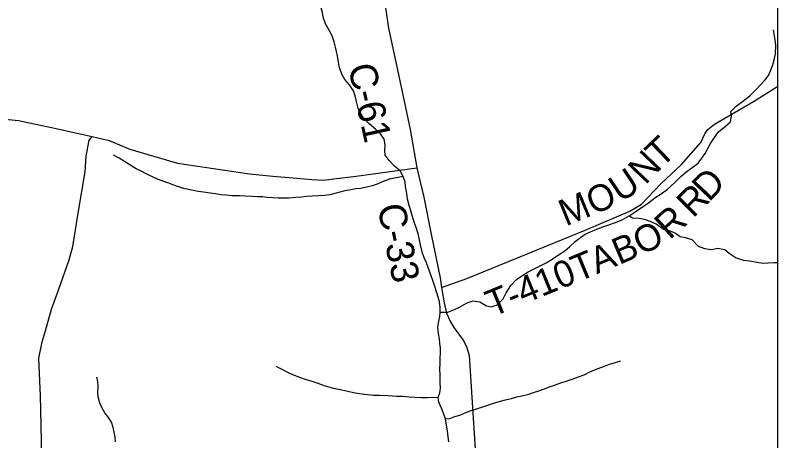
# Model space of a CAD drawing. Extents: x -139 to 835, y 0 to 440.
# Drawn here: x 242.7 to 295.5, y 288.9 to 318.3 of the extents above; entities that cross this region are included whole.
import ezdxf

# ---------------------------------------------------------------- set-up
doc = ezdxf.new("R2010")
doc.units = 0
for name, color, linetype in [('GM_X_County_Road', 7, 'Continuous'), ('GM_X_County_Road_Text', 7, 'Continuous'), ('GM_X_County_Text', 7, 'Continuous'), ('GM_X_Minor_River', 7, 'Continuous'), ('GM_X_Township_Road', 7, 'Continuous'), ('GM_X_Township_Road_Text', 7, 'Continuous'), ('SH_Cut_Line', 7, 'Continuous')]:
    doc.layers.add(name, color=color, linetype=linetype)

msp = doc.modelspace()

# ---------------------------------------------------------------- linework, layer by layer
at = {"layer": 'GM_X_County_Road'}
for points in [[(267.916, 321.522), (268.508, 317.419), (269.147, 314.522), (270.024, 310.408), (270.486, 307.753)], [(241.269, 311.192), (242.908, 311.03), (245.196, 310.545), (247.995, 309.929), (249.19, 309.638), (250.624, 309.055), (253.902, 308.084), (258.899, 307.34), (260.514, 307.178), (261.925, 307.054), (263.209, 306.953), (263.997, 306.903), (264.722, 306.997), (266.287, 307.174), (270.486, 307.753)], [(270.486, 307.753), (270.962, 305.725), (271.487, 303.058), (272.101, 300.138), (272.175, 299.474), (272.375, 298.412), (272.538, 297.712), (272.816, 297.096), (273.043, 296.71), (273.676, 295.827), (273.917, 295.405), (274.092, 294.765), (274.624, 286.489)]]:
    msp.add_lwpolyline(points, dxfattribs=at)
at = {"layer": 'GM_X_County_Text'}
msp.add_lwpolyline([(138.399, 185.387), (295.458, 185.387), (295.458, 319.381), (267.909, 321.538), (228.151, 324.569)], dxfattribs=at)
at = {"layer": 'GM_X_Minor_River'}
for points in [[(264.747, 316.458), (264.616, 316.879), (264.422, 317.227), (264.15, 317.707), (263.993, 318.176), (263.939, 318.489), (263.86, 318.826), (263.818, 319.188), (263.789, 319.585), (263.543, 320.017), (263.057, 320.29), (262.637, 320.299), (262.192, 320.294), (261.848, 320.328), (261.4, 320.553), (261.053, 320.947), (260.795, 321.367), (260.335, 322.107)], [(272.098, 297.781), (272.632, 297.774), (273.089, 297.947), (273.431, 298.119), (273.912, 298.389), (274.356, 298.562), (274.827, 298.482), (275.301, 298.221), (275.62, 298.139), (276.038, 298.276), (276.442, 298.702), (276.667, 299.102), (276.98, 299.623), (277.384, 300.037), (277.75, 300.294), (278.181, 300.563), (278.916, 300.92), (279.422, 301.19), (279.84, 301.435), (280.282, 301.74), (280.712, 302.022), (281.041, 302.29), (281.445, 302.668), (281.799, 302.936), (282.127, 303.168), (282.495, 303.329), (282.926, 303.514), (283.357, 303.674), (283.763, 303.823), (284.169, 303.947), (284.689, 304.157), (285.17, 304.439), (285.663, 304.757), (286.169, 305.111), (286.523, 305.344), (286.94, 305.673), (287.383, 305.967), (287.826, 306.284), (288.343, 306.748), (288.759, 307.149), (289.189, 307.515), (289.517, 307.76), (289.947, 308.089), (290.211, 308.429), (290.437, 308.757), (290.813, 309.436), (291.126, 309.933), (291.365, 310.237), (291.833, 310.627), (292.199, 310.944), (292.246, 311.331), (292.205, 311.656), (292.571, 312.009), (293.026, 312.339), (293.518, 312.73), (293.922, 313.131), (294.288, 313.521), (294.59, 313.837), (294.829, 314.141), (294.966, 314.456), (295.128, 314.867), (295.238, 315.315), (295.299, 315.653), (295.319, 316.172), (295.291, 316.473), (295.224, 316.894), (295.169, 317.304)], [(272.689, 288.8), (272.648, 289.149), (272.593, 289.571), (272.539, 289.968), (272.458, 290.39), (272.302, 290.823), (272.184, 291.135), (272.002, 291.556), (271.961, 291.869), (272.06, 292.196), (272.108, 292.522), (272.092, 292.92), (272.087, 293.426), (272.07, 293.848), (272.092, 294.211), (272.101, 294.609), (272.111, 294.947), (272.108, 295.308), (272.079, 295.61), (272.038, 295.935), (271.984, 296.296), (271.942, 296.73), (271.989, 297.153), (272.062, 297.479), (272.098, 297.781), (272.095, 298.095), (272.04, 298.492), (271.948, 298.805), (271.738, 299.479), (271.607, 299.888), (271.437, 300.357), (271.255, 300.862), (271.137, 301.174), (271.007, 301.487), (270.864, 301.859), (270.731, 302.425), (270.651, 302.786), (270.559, 303.183), (270.427, 303.628), (270.297, 303.989), (270.166, 304.398), (270.06, 304.771), (269.942, 305.156), (269.836, 305.589), (269.782, 305.987), (269.701, 306.456), (269.66, 306.757), (269.542, 307.154), (269.322, 307.551), (268.925, 307.873), (268.552, 308.255), (268.294, 308.639), (268.265, 308.964), (268.287, 309.338), (268.207, 309.736), (267.962, 310.095), (267.616, 310.418), (267.167, 310.787), (266.781, 311.194), (266.549, 311.578), (266.406, 311.89), (266.3, 312.336), (266.207, 312.733), (266.102, 313.082), (265.818, 313.489), (265.496, 313.872), (265.303, 314.196), (265.12, 314.665), (264.985, 315.484), (264.919, 315.797), (264.852, 316.097), (264.747, 316.458)], [(269.542, 307.154), (268.92, 307.04), (268.589, 306.977), (268.158, 306.804), (267.74, 306.631), (267.397, 306.508), (267.004, 306.408), (266.584, 306.331), (266.254, 306.304), (265.911, 306.241), (265.504, 306.153), (265.149, 306.065), (264.463, 305.89), (264.056, 305.838), (263.637, 305.81), (263.242, 305.794), (262.861, 305.767), (262.467, 305.727), (262.098, 305.699), (261.614, 305.659), (261.258, 305.656), (260.889, 305.664), (260.482, 305.672), (260.125, 305.705), (259.794, 305.739), (259.425, 305.759), (259.094, 305.78), (258.584, 305.788), (258.202, 305.809), (257.68, 305.828), (257.26, 305.86), (256.916, 305.893), (256.534, 305.95), (256.164, 305.995), (255.706, 306.063), (255.336, 306.12), (254.89, 306.2), (254.316, 306.328), (253.984, 306.445), (253.665, 306.563), (253.307, 306.693), (252.963, 306.81), (252.643, 306.928), (252.311, 307.07), (251.8, 307.318), (251.391, 307.532), (251.045, 307.697), (250.687, 307.911), (250.316, 308.137), (249.881, 308.422), (249.484, 308.636)], [(285.17, 304.439), (285.413, 304.308), (285.859, 304.276), (286.203, 304.195), (286.663, 304.054), (287.11, 303.829), (287.546, 303.508), (288.018, 303.403), (288.376, 303.226), (288.696, 303.011), (289.053, 302.942), (289.512, 302.802), (289.949, 302.335), (290.396, 302.183), (290.868, 302.115), (291.312, 302.203), (291.784, 302.099), (292.104, 301.849), (292.578, 301.527), (293.076, 301.375), (293.535, 301.331), (294.006, 301.239), (294.44, 301.17), (294.796, 301.186), (295.216, 301.214), (295.458, 301.207)], [(271.961, 291.869), (271.223, 291.838), (270.778, 291.846), (270.358, 291.879), (269.95, 291.899), (269.479, 291.931), (269.084, 291.951), (268.499, 291.982), (267.9, 292.001), (267.48, 292.021), (267.06, 292.066), (266.512, 292.121), (266.091, 292.189), (265.607, 292.306), (265.173, 292.398), (264.714, 292.49), (264.089, 292.678), (263.655, 292.843), (263.233, 292.984), (262.774, 293.124), (262.378, 293.253), (261.906, 293.43), (261.586, 293.584), (261.151, 293.809), (260.742, 294.022)], [(272.458, 290.39), (272.751, 290.429), (273.106, 290.553), (273.449, 290.652), (273.88, 290.825), (274.235, 290.961), (274.679, 291.11), (275.034, 291.222), (275.402, 291.346), (275.872, 291.495), (276.278, 291.619), (276.62, 291.719), (277.027, 291.807), (277.395, 291.907), (277.751, 291.994), (278.22, 292.107), (278.563, 292.207), (278.918, 292.343), (279.248, 292.454), (279.667, 292.615), (279.997, 292.727), (280.377, 292.863), (280.872, 293.024), (281.227, 293.136), (281.671, 293.297), (282.052, 293.445), (282.508, 293.666), (283.027, 293.888), (283.471, 294.049), (283.814, 294.173), (284.131, 294.26), (284.601, 294.397)], [(248.394, 292.981), (248.34, 293.282)], [(249.629, 288.806), (249.588, 289.132), (249.534, 289.481), (249.467, 289.794), (249.336, 290.167), (249.13, 290.478), (248.885, 290.802), (248.704, 291.126), (248.535, 291.486), (248.429, 291.92), (248.401, 292.221), (248.41, 292.607), (248.394, 292.981)]]:
    msp.add_lwpolyline(points, dxfattribs=at)
at = {"layer": 'GM_X_Township_Road'}
for points in [[(272.175, 299.474), (273.945, 300.108), (277.956, 301.737), (282.12, 303.45), (285.227, 304.768), (286.03, 305.236), (287.344, 306.632), (288.798, 307.991), (290.139, 309.506), (290.408, 310.097), (290.625, 310.397), (291.071, 310.782), (293.772, 312.342), (295.404, 313.363), (295.458, 313.407)], [(244.515, 287.564), (244.485, 289.977), (244.428, 291.991), (244.309, 294.597), (244.547, 295.715), (244.786, 296.492), (245.196, 297.982), (245.708, 299.374), (246.425, 301.381), (246.664, 302.32), (247.039, 304.619), (247.517, 307.469), (247.586, 308.569), (247.79, 309.67), (247.995, 309.929)]]:
    msp.add_lwpolyline(points, dxfattribs=at)
at = {"layer": 'SH_Cut_Line'}
msp.add_lwpolyline([(67.578, 336.518), (67.578, 185.387), (295.458, 185.387), (295.458, 319.381), (267.909, 321.538), (228.151, 324.569), (207.436, 326.102), (194.287, 327.176), (177.155, 328.576), (171.559, 329.033), (160.688, 329.921), (158.444, 330.1), (105.67, 333.828), (92.493, 334.759)], close=True, dxfattribs=at)

# ---------------------------------------------------------------- texts
at = {"layer": 'GM_X_County_Road_Text'}
for s, height, rotation, p in [('C-61', 1.9029, 282.4052, (265.709, 314.767)), ('C-33', 1.903, 281.6273, (267.739, 305.087))]:
    msp.add_text(s, height=height, rotation=rotation, dxfattribs=at).set_placement(p)
at = {"layer": 'GM_X_Township_Road_Text'}
for s, height, rotation, p in [('T', 1.873, 43.6406, (287.398, 307.682)), ('N', 1.877, 46.3368, (286.29, 306.52)), ('U', 1.854, 33.796, (284.579, 305.316)), ('D', 1.878, 46.5508, (290.708, 305.345)), ('O', 1.831, 22.5892, (282.681, 304.483)), ('R', 1.875, 44.99, (289.594, 304.229)), ('M', 1.831, 22.4697, (280.782, 303.698)), ('R', 1.87, 42.0461, (287.981, 302.732)), ('O', 1.838, 25.94, (286.006, 301.681)), ('B', 1.832, 23.0222, (284.48, 301.029)), ('A', 1.831, 22.6167, (282.932, 300.385)), ('T', 1.831, 22.5422, (281.625, 299.842)), ('T-410', 1.8304, 22.2233, (275.716, 297.429))]:
    msp.add_text(s, height=height, rotation=rotation, dxfattribs=at).set_placement(p)

doc.saveas('drawing.dxf')
